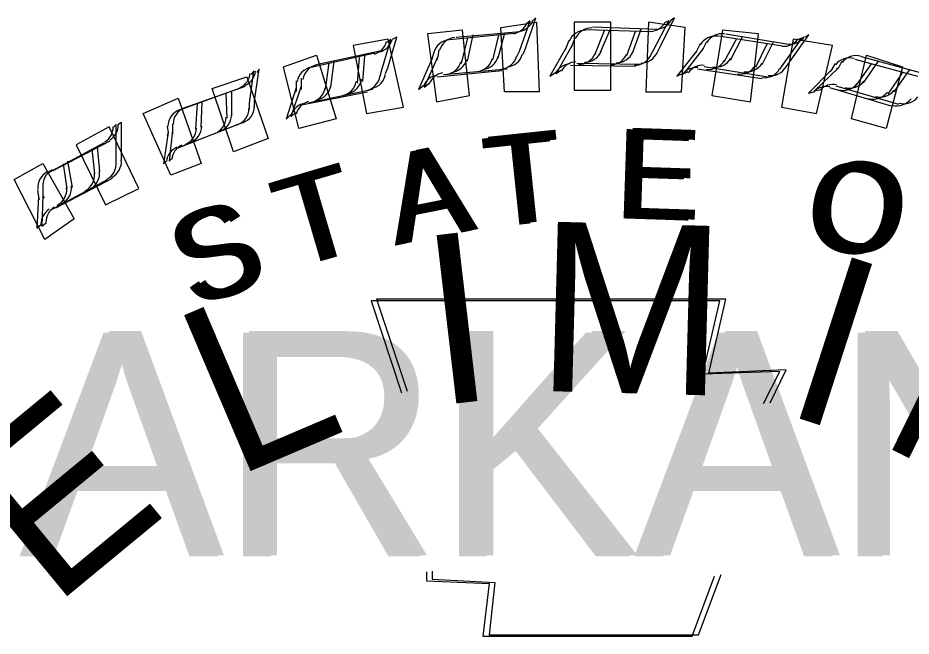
# Model space of a CAD drawing. Extents: x 208.5 to 250.5, y 328.7 to 350.7.
# Drawn here: x 233.787 to 234.537, y 331.698 to 332.216 of the extents above; entities that cross this region are included whole.
import ezdxf

# ---------------------------------------------------------------- set-up
doc = ezdxf.new("R2010")
doc.units = 0
for name, color, linetype in [('Border 2660-Hwy18 - STAMP PRELIM', 7, 'Continuous'), ('Border 2660-Hwy18 - Stamp-ChrisC', 7, 'Continuous'), ('Stamp Charles W', 7, 'Continuous')]:
    doc.layers.add(name, color=color, linetype=linetype)

msp = doc.modelspace()

# ---------------------------------------------------------------- linework, layer by layer
at = {"layer": 'Border 2660-Hwy18 - STAMP PRELIM'}
for p, q in [((234.19248, 332.20814), (234.22248, 332.21264)), ((234.22248, 332.21264), (234.22478, 332.15414)), ((234.28478, 332.21264), (234.25398, 332.21264)), ((234.25398, 332.21264), (234.25398, 332.15564)), ((234.28478, 332.15564), (234.28478, 332.21264)), ((234.31628, 332.21264), (234.31398, 332.15414)), ((234.34698, 332.20814), (234.31628, 332.21264)), ((234.16028, 332.20594), (234.13098, 332.20294)), ((234.13098, 332.20294), (234.13848, 332.14594)), ((234.16628, 332.15114), (234.16028, 332.20594)), ((234.19548, 332.15414), (234.19248, 332.20814)), ((234.34398, 332.15414), (234.34698, 332.20814)), ((234.37848, 332.20594), (234.36948, 332.15114)), ((234.40848, 332.20294), (234.37848, 332.20594)), ((234.40178, 332.14594), (234.40848, 332.20294)), ((234.09798, 332.19844), (234.06878, 332.19314)), ((234.11078, 332.14144), (234.09798, 332.19844)), ((234.43778, 332.19844), (234.42798, 332.14144)), ((234.47078, 332.19314), (234.43778, 332.19844)), ((234.06878, 332.19314), (234.07998, 332.13614)), ((234.45728, 332.13614), (234.47078, 332.19314)), ((234.01028, 332.17514), (234.03798, 332.18494)), ((234.03798, 332.18494), (234.05448, 332.13164)), ((234.48648, 332.13164), (234.49928, 332.18494)), ((234.49928, 332.18494), (234.52928, 332.17514)), ((234.02298, 332.12344), (234.01028, 332.17514)), ((234.52928, 332.17514), (234.51578, 332.12344)), ((233.95028, 332.15714), (233.97948, 332.16694)), ((233.97948, 332.16694), (233.99748, 332.11514)), ((233.96828, 332.10394), (233.95028, 332.15714)), ((234.13848, 332.14594), (234.16628, 332.15114)), ((234.22478, 332.15414), (234.19548, 332.15414)), ((234.25398, 332.15564), (234.28478, 332.15564)), ((234.31398, 332.15414), (234.34398, 332.15414)), ((234.36948, 332.15114), (234.40178, 332.14594)), ((233.89248, 332.13614), (233.92178, 332.14894)), ((233.92178, 332.14894), (233.94128, 332.09414)), ((233.91578, 332.08444), (233.89248, 332.13614)), ((234.07998, 332.13614), (234.11078, 332.14144)), ((234.42798, 332.14144), (234.45728, 332.13614)), ((234.05448, 332.13164), (234.02298, 332.12344)), ((234.51578, 332.12344), (234.48648, 332.13164)), ((233.86398, 332.12494), (233.83628, 332.10994)), ((233.88878, 332.07314), (233.86398, 332.12494)), ((233.99748, 332.11514), (233.96828, 332.10394)), ((233.83628, 332.10994), (233.86098, 332.05964)), ((233.78448, 332.08064), (233.80848, 332.09414)), ((233.80848, 332.09414), (233.83478, 332.04764)), ((233.94128, 332.09414), (233.91578, 332.08444)), ((233.80998, 332.03044), (233.78448, 332.08064)), ((233.86098, 332.05964), (233.88878, 332.07314)), ((233.83478, 332.04764), (233.80998, 332.03044))]:
    msp.add_line(p, q, dxfattribs=at)
at = {"layer": 'Border 2660-Hwy18 - Stamp-ChrisC'}
for p, q in [((234.20823, 332.18839), (234.21723, 332.21389)), ((234.21723, 332.21389), (234.21423, 332.21159)), ((234.32073, 332.18989), (234.33343, 332.21389)), ((234.33343, 332.21389), (234.33043, 332.21239)), ((234.14973, 332.19809), (234.20373, 332.20339)), ((234.26443, 332.20639), (234.31843, 332.20489)), ((234.27123, 332.18539), (234.27943, 332.20559)), ((234.29823, 332.18459), (234.30573, 332.20559)), ((234.09273, 332.17259), (234.10023, 332.19809)), ((234.10023, 332.19809), (234.09723, 332.19589)), ((234.15943, 332.17789), (234.16473, 332.19959)), ((234.18573, 332.18089), (234.19093, 332.20189)), ((234.24943, 332.19739), (234.24723, 332.19139)), ((234.37543, 332.20109), (234.42873, 332.19289)), ((234.37993, 332.17939), (234.39043, 332.19889)), ((234.42943, 332.17709), (234.44523, 332.19959)), ((234.44523, 332.19959), (234.44223, 332.19809)), ((234.20593, 332.18389), (234.20823, 332.18839)), ((234.24723, 332.19139), (234.23373, 332.16739)), ((234.24723, 332.19139), (234.24643, 332.18909)), ((234.31843, 332.18539), (234.32073, 332.18989)), ((234.35673, 332.18839), (234.34023, 332.16739)), ((234.35673, 332.18839), (234.35593, 332.18689)), ((234.35973, 332.19439), (234.35673, 332.18839)), ((234.40623, 332.17489), (234.41593, 332.19439)), ((234.03343, 332.17489), (234.08673, 332.18689)), ((234.07243, 332.16139), (234.07393, 332.18309)), ((234.13473, 332.18159), (234.12343, 332.15609)), ((234.13473, 332.18159), (234.13393, 332.17939)), ((234.13623, 332.18759), (234.13473, 332.18159)), ((234.48943, 332.18159), (234.54193, 332.16739)), ((234.04543, 332.15609), (234.04843, 332.17859)), ((234.30573, 332.17559), (234.25093, 332.17639)), ((234.41143, 332.16509), (234.35743, 332.17339)), ((234.42643, 332.17339), (234.42943, 332.17709)), ((234.47293, 332.17789), (234.46993, 332.17259)), ((234.49093, 332.15989), (234.50373, 332.17789)), ((233.98173, 332.14489), (233.98543, 332.17189)), ((233.98543, 332.17189), (233.98323, 332.16889)), ((234.09123, 332.16739), (234.09273, 332.17259)), ((234.19323, 332.17189), (234.13923, 332.16659)), ((234.23373, 332.16739), (234.23823, 332.17039)), ((234.34023, 332.16739), (234.34473, 332.16959)), ((234.46993, 332.17259), (234.45043, 332.15309)), ((234.46993, 332.17259), (234.46843, 332.17109)), ((234.51723, 332.15239), (234.52993, 332.17109)), ((234.02073, 332.16359), (234.02073, 332.15759)), ((234.12343, 332.15609), (234.12793, 332.15989)), ((233.92243, 332.13889), (233.97423, 332.15759)), ((233.96293, 332.13209), (233.96223, 332.15309)), ((234.02073, 332.15759), (234.01243, 332.13139)), ((234.02073, 332.15759), (234.02073, 332.15459)), ((234.08073, 332.15389), (234.02673, 332.14339)), ((234.45043, 332.15309), (234.45573, 332.15459)), ((234.52093, 332.14189), (234.46843, 332.15759)), ((233.93673, 332.12309), (233.93823, 332.14409)), ((233.98173, 332.13959), (233.98173, 332.14489)), ((234.01243, 332.13139), (234.01623, 332.13509)), ((233.86993, 332.12689), (233.86773, 332.12459)), ((233.86993, 332.10059), (233.86993, 332.12689)), ((233.91273, 332.12539), (233.91343, 332.12009)), ((233.97193, 332.12689), (233.92023, 332.10659)), ((233.91343, 332.12009), (233.90973, 332.09389)), ((233.91343, 332.12009), (233.91273, 332.11709)), ((233.81293, 332.08639), (233.86023, 332.11189)), ((233.85193, 332.08559), (233.84973, 332.10659)), ((233.86993, 332.09539), (233.86993, 332.10059)), ((233.82873, 332.07289), (233.82573, 332.09389)), ((233.90973, 332.09389), (233.91273, 332.09689)), ((233.86243, 332.08039), (233.81443, 332.05489)), ((233.80393, 332.07209), (233.80473, 332.06609)), ((233.80473, 332.06609), (233.80323, 332.03989)), ((233.80473, 332.06609), (233.80543, 332.06389)), ((233.80323, 332.03989), (233.80693, 332.04289))]:
    msp.add_line(p, q, dxfattribs=at)
for points in [[(234.08373, 331.97909), (234.10923, 331.90189)], [(234.41293, 331.89289), (234.42643, 331.91989), (234.36193, 331.91759), (234.37623, 331.97909), (234.08373, 331.97909)], [(234.13023, 331.75189), (234.13023, 331.74439), (234.18273, 331.74209), (234.17743, 331.69789), (234.35293, 331.69789), (234.37173, 331.74809)]]:
    msp.add_lwpolyline(points, dxfattribs=at)
for centre, start, end in [((234.20063, 332.2176), 279.92492, 338.71276), ((234.31726, 332.21964), 273.42361, 332.21146), ((234.26358, 332.19112), 89.16284, 157.53681), ((234.08236, 332.20016), 286.27006, 345.0579), ((234.15052, 332.18319), 95.66414, 164.03812), ((234.37261, 332.18622), 81.42307, 149.79704), ((234.42964, 332.20725), 265.68385, 324.47169), ((234.17107, 332.18599), 275.66414, 344.03812), ((234.1915, 332.18807), 275.66414, 344.03812), ((234.25789, 332.19206), 269.16284, 337.53681), ((234.28432, 332.19157), 269.16284, 337.53681), ((234.30485, 332.19134), 269.16284, 337.53681), ((234.3671, 332.18791), 261.42307, 329.79704), ((234.48489, 332.16791), 73.99093, 142.3649), ((234.03637, 332.16042), 102.00928, 170.38325), ((234.14476, 332.18348), 275.66414, 344.03812), ((234.25117, 332.16282), 93.42361, 152.21146), ((234.3565, 332.15984), 85.68385, 144.47169), ((234.39322, 332.18387), 261.42307, 329.79704), ((234.41353, 332.18087), 261.42307, 329.79704), ((233.96767, 332.17138), 294.83706, 353.62491), ((234.07656, 332.1698), 282.00928, 350.38325), ((234.14139, 332.15366), 99.92492, 158.71276), ((234.05649, 332.16547), 282.00928, 350.38325), ((234.46551, 332.14384), 78.25171, 137.03955), ((234.47964, 332.1703), 253.99093, 322.3649), ((234.03061, 332.16007), 282.00928, 350.38325), ((234.50503, 332.16291), 253.99093, 322.3649), ((234.03056, 332.13006), 106.27006, 165.0579), ((234.52478, 332.15731), 253.99093, 322.3649), ((233.92811, 332.12523), 110.57629, 178.95026), ((233.96645, 332.1405), 290.57629, 358.95026), ((233.94725, 332.13322), 290.57629, 358.95026), ((233.85258, 332.12481), 301.95449, 0.74233), ((233.92246, 332.12403), 290.57629, 358.95026), ((233.92689, 332.09435), 114.83706, 173.62491), ((233.8552, 332.09401), 297.69371, 6.06769), ((233.81904, 332.07411), 117.69371, 186.06769), ((233.83704, 332.08441), 297.69371, 6.06769), ((233.81359, 332.07222), 297.69371, 6.06769), ((233.82165, 332.04332), 121.95449, 180.74233)]:
    msp.add_arc(centre, 0.01481, start, end, dxfattribs=at)
at = {"layer": 'Stamp Charles W'}
for p, q in [((234.21318, 332.1905), (234.22177, 332.21627)), ((234.22177, 332.21627), (234.21891, 332.21341)), ((234.32582, 332.19145), (234.33823, 332.21627)), ((234.33823, 332.21627), (234.33537, 332.21437)), ((234.15495, 332.20005), (234.2084, 332.20482)), ((234.19027, 332.18286), (234.19599, 332.20386)), ((234.2695, 332.20864), (234.32391, 332.20673)), ((234.27618, 332.18764), (234.28477, 332.20768)), ((234.30291, 332.18668), (234.31055, 332.20768)), ((234.38119, 332.20291), (234.4337, 332.19432)), ((234.09767, 332.17427), (234.1053, 332.20005)), ((234.1053, 332.20005), (234.10149, 332.19814)), ((234.16449, 332.18), (234.16926, 332.20196)), ((234.25423, 332.19909), (234.25232, 332.19336)), ((234.36496, 332.19623), (234.3621, 332.1905)), ((234.38501, 332.18095), (234.39551, 332.201)), ((234.41174, 332.17714), (234.42129, 332.19623)), ((234.43465, 332.17904), (234.45088, 332.20196)), ((234.45088, 332.20196), (234.44802, 332.20005)), ((234.03753, 332.17714), (234.09099, 332.18859)), ((234.14063, 332.18955), (234.13967, 332.18382)), ((234.21127, 332.18573), (234.21318, 332.1905)), ((234.25232, 332.19336), (234.23895, 332.1695)), ((234.25232, 332.19336), (234.25136, 332.19145)), ((234.32391, 332.18764), (234.32582, 332.19145)), ((234.3621, 332.1905), (234.34587, 332.1695)), ((234.3621, 332.1905), (234.36114, 332.18859)), ((234.07667, 332.16282), (234.07858, 332.18477)), ((234.13967, 332.18382), (234.12822, 332.15804)), ((234.13967, 332.18382), (234.13872, 332.18095)), ((234.49479, 332.18382), (234.5473, 332.1695)), ((233.98598, 332.14659), (233.98979, 332.17332)), ((233.98979, 332.17332), (233.98789, 332.17045)), ((234.04994, 332.15804), (234.0528, 332.18)), ((234.09576, 332.1695), (234.09767, 332.17427)), ((234.1979, 332.17332), (234.14444, 332.16854)), ((234.31055, 332.17714), (234.25614, 332.17809)), ((234.41651, 332.16663), (234.36305, 332.17523)), ((234.43179, 332.17523), (234.43465, 332.17904)), ((234.4757, 332.17427), (234.45565, 332.15518)), ((234.4757, 332.17427), (234.47379, 332.17332)), ((234.47856, 332.18), (234.4757, 332.17427)), ((234.4967, 332.16186), (234.50911, 332.18)), ((234.52248, 332.15422), (234.53584, 332.17332)), ((234.02512, 332.16568), (234.02512, 332.159)), ((234.23895, 332.1695), (234.24277, 332.17236)), ((234.34587, 332.1695), (234.34969, 332.17141)), ((233.92679, 332.14086), (233.97834, 332.159)), ((234.02512, 332.159), (234.01652, 332.13322)), ((234.02512, 332.159), (234.02512, 332.15613)), ((234.12822, 332.15804), (234.13299, 332.16186)), ((234.5263, 332.14372), (234.47379, 332.159)), ((233.96688, 332.13418), (233.96688, 332.15518)), ((234.08526, 332.15613), (234.03084, 332.14468)), ((234.45565, 332.15518), (234.46138, 332.15613)), ((233.94111, 332.12463), (233.94206, 332.14563)), ((233.98598, 332.14181), (233.98598, 332.14659)), ((234.01652, 332.13322), (234.02034, 332.13704)), ((233.87429, 332.12845), (233.87142, 332.12654)), ((233.87429, 332.10267), (233.87429, 332.12845)), ((233.97643, 332.12845), (233.92488, 332.1084)), ((233.91724, 332.12177), (233.91438, 332.09599)), ((233.91724, 332.12749), (233.91724, 332.12177)), ((233.91724, 332.12177), (233.91724, 332.1189)), ((233.81701, 332.08835), (233.86474, 332.11318)), ((233.85615, 332.0874), (233.85424, 332.1084)), ((233.87429, 332.09695), (233.87429, 332.10267)), ((233.91438, 332.09599), (233.91724, 332.09886)), ((233.83324, 332.07404), (233.82942, 332.09599)), ((233.86665, 332.08167), (233.81892, 332.05685)), ((233.80842, 332.07404), (233.80842, 332.06735)), ((233.80842, 332.06735), (233.80746, 332.04158)), ((233.80842, 332.06735), (233.80937, 332.06544)), ((233.80746, 332.04158), (233.81128, 332.04444))]:
    msp.add_line(p, q, dxfattribs=at)
for points in [[(234.08812, 331.98048), (234.1139, 331.90316)], [(234.41842, 331.89361), (234.43179, 331.9213), (234.36687, 331.91843), (234.38119, 331.98048), (234.08812, 331.98048)], [(234.1349, 331.75233), (234.1349, 331.74564), (234.1874, 331.74278), (234.18263, 331.69887), (234.35828, 331.69887), (234.37737, 331.74946)]]:
    msp.add_lwpolyline(points, dxfattribs=at)
for centre, start, end in [((234.20561, 332.21956), 279.92492, 338.71276), ((234.32251, 332.2216), 273.42361, 332.21146), ((234.2687, 332.19302), 89.16284, 157.53681), ((234.37798, 332.18811), 81.42307, 149.79704), ((234.08708, 332.20208), 286.27006, 345.0579), ((234.15539, 332.18507), 95.66414, 164.03812), ((234.43514, 332.20918), 265.68385, 324.47169), ((234.263, 332.19396), 269.16284, 337.53681), ((234.14961, 332.18536), 275.66414, 344.03812), ((234.17599, 332.18787), 275.66414, 344.03812), ((234.19646, 332.18997), 275.66414, 344.03812), ((234.28949, 332.19348), 269.16284, 337.53681), ((234.31007, 332.19324), 269.16284, 337.53681), ((234.37245, 332.18981), 261.42307, 329.79704), ((234.49051, 332.16975), 73.99093, 142.3649), ((234.04098, 332.16225), 102.00928, 170.38325), ((234.25626, 332.16465), 93.42361, 152.21146), ((234.36183, 332.16167), 85.68385, 144.47169), ((234.39864, 332.18575), 261.42307, 329.79704), ((234.41899, 332.18275), 261.42307, 329.79704), ((233.97214, 332.17323), 294.83706, 353.62491), ((234.08126, 332.17165), 282.00928, 350.38325), ((234.14624, 332.15548), 99.92492, 158.71276), ((234.03521, 332.1619), 282.00928, 350.38325), ((234.06115, 332.16731), 282.00928, 350.38325), ((234.47108, 332.14563), 78.25171, 137.03955), ((234.48525, 332.17216), 253.99093, 322.3649), ((234.51069, 332.16475), 253.99093, 322.3649), ((234.03516, 332.13182), 106.27006, 165.0579), ((234.53049, 332.15913), 253.99093, 322.3649), ((233.93248, 332.12698), 110.57629, 178.95026), ((233.97091, 332.14228), 290.57629, 358.95026), ((233.95167, 332.13499), 290.57629, 358.95026), ((233.85679, 332.12656), 301.95449, 0.74233), ((233.92683, 332.12578), 290.57629, 358.95026), ((233.93126, 332.09603), 114.83706, 173.62491), ((233.85941, 332.09569), 297.69371, 6.06769), ((233.82317, 332.07575), 117.69371, 186.06769), ((233.84122, 332.08608), 297.69371, 6.06769), ((233.81771, 332.07385), 297.69371, 6.06769), ((233.82579, 332.04489), 121.95449, 180.74233)]:
    msp.add_arc(centre, 0.01484, start, end, dxfattribs=at)

# ---------------------------------------------------------------- texts
at = {"layer": 'Border 2660-Hwy18 - STAMP PRELIM'}
for s, rotation, p in [('M', 358.46666, (234.22098, 331.90364)), ('I', 6.67523, (234.13778, 331.89094)), ('I', 342.04953, (234.42648, 331.88564)), ('N', 333.84096, (234.50678, 331.86094)), ('L', 23.09236, (233.96828, 331.83014)), ('E', 39.5095, (233.81678, 331.72144))]:
    msp.add_text(s, height=0.14209, rotation=rotation, dxfattribs=at).set_placement(p)
at = {"layer": 'Border 2660-Hwy18 - Stamp-ChrisC'}
for s, height, rotation, p in [('T', 0.075, 6.02276, (234.18223, 332.04019)), ('E', 0.07499, 358.07323, (234.28723, 332.04839)), ('A', 0.075, 11.21318, (234.10343, 332.02519)), ('T', 0.07499, 16.4036, (234.01643, 332.00489)), ('O', 0.07498, 350.4515, (234.44393, 332.02589)), ('S', 0.07499, 21.59401, (233.93393, 331.97189))]:
    msp.add_text(s, height=height, rotation=rotation, dxfattribs=at).set_placement(p)
msp.add_text('ARKANSAS', height=0.187497, dxfattribs=at).set_placement((233.78843, 331.76489))
at = {"layer": 'Stamp Charles W'}
for s, height, rotation, p in [('T', 0.07517, 6.02276, (234.1874, 332.04158)), ('E', 0.07515, 358.07323, (234.29241, 332.04922)), ('A', 0.07517, 11.21318, (234.10817, 332.0263)), ('O', 0.07514, 350.4515, (234.44992, 332.02726)), ('T', 0.07515, 16.4036, (234.0213, 332.00626)), ('S', 0.07515, 21.59401, (233.9392, 331.97285))]:
    msp.add_text(s, height=height, rotation=rotation, dxfattribs=at).set_placement(p)
msp.add_text('ARKANSAS', height=0.187911, dxfattribs=at).set_placement((233.79314, 331.76569))

doc.saveas('drawing.dxf')
